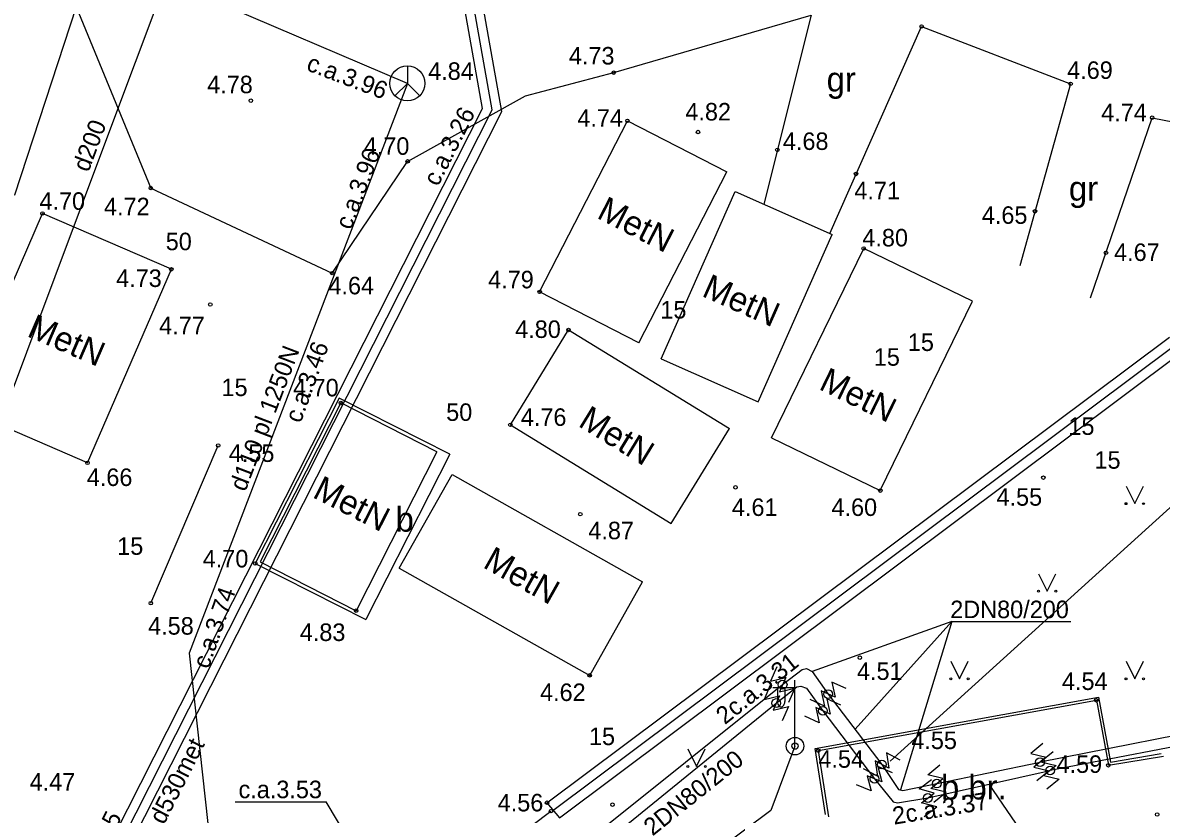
# Model space of a CAD drawing. Extents: x 484635 to 484808, y 278866 to 278977.
# Drawn here: x 484755.78 to 484788.25, y 278898.63 to 278921.23 of the extents above; entities that cross this region are included whole.
import ezdxf

# ---------------------------------------------------------------- set-up
doc = ezdxf.new("R2010")
doc.units = 0
for name, color, linetype in [('APGS_ACRL_####_####_#', 7, 'Continuous'), ('APGS_ELEM_####_####_#', 7, 'Continuous'), ('APGS_VADP_ZSPR_####_I', 7, 'Continuous'), ('BUVE_EKAS_BPAL_####_#', 7, 'Continuous'), ('BUVE_EKAS_RAKS_TKST_#', 7, 'Continuous'), ('CELI_CAPM_####_####_#', 7, 'Continuous'), ('CELI_CMAL_####_####_#', 7, 'Continuous'), ('CELI_CSEG_####_TKST_#', 7, 'Continuous'), ('CKOM_ELEM_####_####_#', 7, 'Continuous'), ('ELEK_VADP_NEDR_####_#', 7, 'Continuous'), ('GAZE_VADP_KONT_####_#', 7, 'Continuous'), ('GAZE_VADP_VSP2_####_#', 7, 'Continuous'), ('GAZE_VADP_VSP2_TKST_#', 7, 'Continuous'), ('NORB_ZOGS_KONT_####_#', 7, 'Continuous'), ('NORB_ZOGS_ZSTP_####_#', 7, 'Continuous'), ('RELJ_AATZ_####_TKST_#', 7, 'Continuous'), ('RELJ_ELEM_####_####_#', 7, 'Continuous'), ('SAKK_ELEM_####_####_#', 7, 'Continuous'), ('SAKK_ELEM_####_TKST_#', 7, 'Continuous'), ('SAKK_KKAN_####_####_I', 7, 'Continuous'), ('SAKK_KKAN_####_TKST_I', 7, 'Continuous'), ('SILT_VADP_UDEN_####_I', 7, 'Continuous'), ('SILT_VADP_UDEN_TKST_I', 7, 'Continuous'), ('SKAN_VADP_NEDR_####_#', 7, 'Continuous'), ('SKAN_VADP_NEDR_TKST_#', 7, 'Continuous'), ('TERT_DIAM_####_TKST_#', 7, 'Continuous'), ('TERT_ELEM_####_####_#', 7, 'Continuous'), ('TERT_KOKR_####_####_#', 7, 'Continuous')]:
    doc.layers.add(name, color=color, linetype=linetype)

msp = doc.modelspace()

# ---------------------------------------------------------------- linework, layer by layer
at = {"layer": 'APGS_ACRL_####_####_#'}
msp.add_lwpolyline([(484777.807, 278900.58), (484777.114, 278898.745), (484769.642, 278893.153), (484768.844, 278885.007), (484767.749, 278872.905), (484767.227, 278866.043)], dxfattribs=at)
at = {"layer": 'APGS_ELEM_####_####_#'}
for p, q in [((484777.807, 278902.247), (484777.172, 278902.242)), ((484777.307, 278902.243), (484777.307, 278901.851)), ((484777.517, 278902.245), (484777.517, 278901.851)), ((484777.807, 278900.58), (484777.807, 278902.463))]:
    msp.add_line(p, q, dxfattribs=at)
for radius in [0.25, 0.09]:
    msp.add_circle((484777.807, 278900.58), radius, dxfattribs=at)
msp.add_ellipse((484777.412, 278901.851), major_axis=(0, 0.151), ratio=0.695971, start_param=1.570796, end_param=4.712389, dxfattribs=at)
at = {"layer": 'APGS_VADP_ZSPR_####_I'}
msp.add_lwpolyline([(484777.807, 278900.58), (484777.114, 278898.745), (484769.642, 278893.153), (484768.844, 278885.007), (484767.749, 278872.905), (484767.227, 278866.043)], dxfattribs=at)
at = {"layer": 'BUVE_EKAS_BPAL_####_#'}
for p, q in [((484770.523, 278913.544), (484773.028, 278918.428)), ((484773.028, 278918.428), (484775.862, 278916.974)), ((484773.356, 278912.09), (484775.862, 278916.974)), ((484773.993, 278911.633), (484776.103, 278916.406)), ((484776.103, 278916.406), (484778.869, 278915.184)), ((484753.95, 278910.258), (484756.344, 278915.783)), ((484760.02, 278914.19), (484756.344, 278915.783)), ((484776.758, 278910.41), (484778.869, 278915.184)), ((484777.139, 278909.381), (484779.767, 278914.783)), ((484782.868, 278913.275), (484779.767, 278914.783)), ((484757.626, 278908.665), (484760.02, 278914.19)), ((484773.356, 278912.09), (484770.523, 278913.544)), ((484780.241, 278907.873), (484782.868, 278913.275)), ((484769.688, 278909.75), (484771.348, 278912.459)), ((484771.348, 278912.459), (484775.94, 278909.646)), ((484773.993, 278911.633), (484776.758, 278910.41)), ((484767.594, 278908.983), (484764.851, 278910.375)), ((484757.626, 278908.665), (484753.95, 278910.258)), ((484769.688, 278909.75), (484774.28, 278906.937)), ((484774.28, 278906.937), (484775.94, 278909.646)), ((484777.139, 278909.381), (484780.241, 278907.873)), ((484767.594, 278908.983), (484765.291, 278904.445)), ((484766.52, 278905.658), (484768.024, 278908.328)), ((484768.024, 278908.328), (484773.455, 278905.269)), ((484762.548, 278905.837), (484765.291, 278904.445)), ((484766.52, 278905.658), (484771.951, 278902.599)), ((484771.951, 278902.599), (484773.455, 278905.269))]:
    msp.add_line(p, q, dxfattribs=at)
msp.add_lwpolyline([(484764.851, 278910.375), (484762.548, 278905.837)], dxfattribs=at)
at = {"layer": 'CELI_CAPM_####_####_#'}
for p, q in [((484778.384, 278900.515), (484786.469, 278901.98)), ((484778.475, 278900.45), (484786.405, 278901.887)), ((484786.405, 278901.887), (484786.747, 278900.033)), ((484786.469, 278901.98), (484786.811, 278900.125)), ((484778.68, 278898.628), (484778.384, 278900.515)), ((484778.771, 278898.563), (484778.475, 278900.45)), ((484786.747, 278900.033), (484788.317, 278900.296)), ((484786.811, 278900.125), (484788.255, 278900.367))]:
    msp.add_line(p, q, dxfattribs=at)
at = {"layer": 'CELI_CMAL_####_####_#'}
for p, q in [((484764.807, 278910.509), (484762.414, 278905.793)), ((484767.959, 278908.91), (484764.807, 278910.509)), ((484767.959, 278908.91), (484765.565, 278904.194)), ((484762.414, 278905.793), (484765.565, 278904.194))]:
    msp.add_line(p, q, dxfattribs=at)
for points in [[(484757.301, 278921.684), (484755.548, 278916.308), (484754.577, 278916.086)], [(484757.301, 278921.684), (484759.431, 278916.509), (484764.605, 278914.081)], [(484764.605, 278914.081), (484766.759, 278917.269), (484770.124, 278919.136), (484772.638, 278919.804), (484778.27, 278921.442), (484776.916, 278916.047)], [(484778.797, 278915.215), (484781.421, 278921.121), (484785.669, 278919.483)], [(484785.669, 278919.483), (484784.22, 278914.284)], [(484786.236, 278913.375), (484787.997, 278918.515), (484788.633, 278918.391)]]:
    msp.add_lwpolyline(points, dxfattribs=at)
at = {"layer": 'CKOM_ELEM_####_####_#'}
for points in [[(484777.29, 278902.847), (484777.109, 278902.438), (484777.545, 278902.539), (484777.365, 278902.129), (484777.8, 278902.231), (484777.62, 278901.821)], [(484777.104, 278902.32), (484776.928, 278901.909), (484777.362, 278902.015), (484777.186, 278901.604), (484777.62, 278901.709), (484777.444, 278901.298)], [(484779.268, 278902.223), (484778.861, 278902.409), (484778.956, 278901.972), (484778.55, 278902.158), (484778.645, 278901.721), (484778.238, 278901.907)], [(484779.12, 278901.744), (484778.714, 278901.932), (484778.808, 278901.494), (484778.402, 278901.682), (484778.496, 278901.244), (484778.09, 278901.432)], [(484784.882, 278900.653), (484784.536, 278900.371), (484784.97, 278900.263), (484784.623, 278899.98), (484785.057, 278899.873), (484784.711, 278899.59)], [(484780.812, 278900.176), (484780.419, 278900.389), (484780.485, 278899.947), (484780.091, 278900.159), (484780.157, 278899.717), (484779.764, 278899.93)], [(484785.173, 278900.416), (484784.825, 278900.135), (484785.258, 278900.025), (484784.91, 278899.744), (484785.344, 278899.634), (484784.996, 278899.353)], [(484780.587, 278899.821), (484780.175, 278899.995), (484780.283, 278899.561), (484779.871, 278899.735), (484779.979, 278899.301), (484779.567, 278899.475)], [(484781.772, 278898.978), (484782.117, 278899.262), (484781.682, 278899.368), (484782.028, 278899.652), (484781.593, 278899.758), (484781.938, 278900.042)], [(484781.496, 278898.57), (484781.852, 278898.842), (484781.421, 278898.963), (484781.777, 278899.235), (484781.346, 278899.356), (484781.702, 278899.628)]]:
    msp.add_lwpolyline(points, dxfattribs=at)
for centre in [(484777.455, 278902.334), (484778.753, 278902.065), (484777.274, 278901.809), (484778.605, 278901.588), (484784.797, 278900.122), (484780.288, 278900.053), (484785.084, 278899.884), (484780.077, 278899.648), (484781.855, 278899.51), (484781.599, 278899.099)]:
    msp.add_circle(centre, 0.125, dxfattribs=at)
at = {"layer": 'ELEK_VADP_NEDR_####_#'}
msp.add_lwpolyline([(484780.522, 278900.153), (484790.322, 278909.033)], dxfattribs=at)
at = {"layer": 'GAZE_VADP_KONT_####_#'}
for points in [[(484750.477, 278882.479), (484757.277, 278895.824), (484768.894, 278918.779), (484766.279, 278933.523), (484765.094, 278950.654), (484769.76, 278961.533)], [(484751.36, 278883.044), (484757.749, 278895.584), (484769.446, 278918.697), (484766.805, 278933.587), (484765.632, 278950.562), (484770.25, 278961.331)]]:
    msp.add_lwpolyline(points, dxfattribs=at)
at = {"layer": 'GAZE_VADP_VSP2_####_#'}
msp.add_lwpolyline([(484750.918, 278882.762), (484757.513, 278895.704), (484769.17, 278918.738), (484766.542, 278933.555), (484765.363, 278950.608), (484770.005, 278961.432)], dxfattribs=at)
at = {"layer": 'NORB_ZOGS_KONT_####_#'}
for p, q in [((484770.732, 278898.963), (484788.487, 278912.252)), ((484771.089, 278898.537), (484788.785, 278911.787)), ((484770.732, 278898.963), (484771.089, 278898.537))]:
    msp.add_line(p, q, dxfattribs=at)
at = {"layer": 'NORB_ZOGS_ZSTP_####_#'}
msp.add_line((484770.897, 278898.742), (484788.636, 278912.019), dxfattribs=at)
msp.add_lwpolyline([(484754.908, 278886.695), (484770.847, 278898.725)], dxfattribs=at)
at = {"layer": 'RELJ_ELEM_####_####_#'}
for centre in [(484781.421, 278921.121), (484772.638, 278919.804), (484785.669, 278919.483), (484762.287, 278919.003), (484773.028, 278918.428), (484787.997, 278918.515), (484775.039, 278918.107), (484777.306, 278917.598), (484766.759, 278917.269), (484779.55, 278916.91), (484759.431, 278916.509), (484756.344, 278915.783), (484784.655, 278915.845), (484779.767, 278914.783), (484786.677, 278914.66), (484760.02, 278914.19), (484764.605, 278914.081), (484770.523, 278913.544), (484761.128, 278913.183), (484771.348, 278912.459), (484764.851, 278910.375), (484769.688, 278909.75), (484761.352, 278909.162), (484757.626, 278908.665), (484776.109, 278907.965), (484784.892, 278908.244), (484780.241, 278907.873), (484771.683, 278907.201), (484762.414, 278905.793), (484759.435, 278904.659), (484765.291, 278904.445), (484779.656, 278903.104), (484771.951, 278902.599), (484786.405, 278901.887), (484778.475, 278900.45), (484786.747, 278900.033), (484770.732, 278898.963), (484772.602, 278898.907), (484770.847, 278898.725), (484788.14, 278898.629)]:
    msp.add_circle(centre, 0.05, dxfattribs=at)
at = {"layer": 'SAKK_ELEM_####_####_#'}
msp.add_line((484766.75, 278919.495), (484767.104, 278919.141), dxfattribs=at)
msp.add_lwpolyline([(484766.75, 278919.995), (484766.75, 278919.495), (484766.396, 278919.141)], dxfattribs=at)
msp.add_circle((484766.75, 278919.495), 0.5, dxfattribs=at)
at = {"layer": 'SAKK_KKAN_####_####_I'}
msp.add_line((484766.75, 278919.495), (484754.941, 278924.541), dxfattribs=at)
for points in [[(484766.75, 278919.495), (484760.526, 278903.237)], [(484760.526, 278903.237), (484761.675, 278892.732), (484761.895, 278888.193)]]:
    msp.add_lwpolyline(points, dxfattribs=at)
at = {"layer": 'SILT_VADP_UDEN_####_I'}
for p, q in [((484768.082, 278894.84), (484777.455, 278902.334)), ((484767.961, 278894.241), (484777.274, 278901.809))]:
    msp.add_line(p, q, dxfattribs=at)
for points in [[(484777.455, 278902.334), (484778.009, 278902.769), (484778.133, 278902.792), (484778.293, 278902.707), (484778.753, 278902.065)], [(484777.274, 278901.809), (484777.856, 278902.276), (484777.975, 278902.291), (484778.134, 278902.229), (484778.605, 278901.588)], [(484796.569, 278902.446), (484784.797, 278900.122)], [(484796.869, 278902.149), (484785.084, 278899.884)], [(484778.753, 278902.065), (484780.288, 278900.053)], [(484778.605, 278901.588), (484780.077, 278899.648)], [(484780.288, 278900.053), (484780.76, 278899.342), (484780.884, 278899.313), (484781.855, 278899.51)], [(484781.599, 278899.099), (484785.084, 278899.884)], [(484781.855, 278899.51), (484784.797, 278900.122)], [(484780.077, 278899.648), (484780.611, 278898.991), (484780.736, 278898.957), (484781.599, 278899.099)]]:
    msp.add_lwpolyline(points, dxfattribs=at)
at = {"layer": 'SILT_VADP_UDEN_TKST_I'}
for p, q in [((484782.278, 278904.139), (484778.293, 278902.707)), ((484782.278, 278904.139), (484779.521, 278901.059)), ((484782.278, 278904.139), (484780.822, 278899.328)), ((484782.278, 278904.139), (484785.674, 278904.139)), ((484761.842, 278898.988), (484764.438, 278898.988)), ((484767.585, 278893.684), (484764.438, 278898.988))]:
    msp.add_line(p, q, dxfattribs=at)
msp.add_lwpolyline([(484784.493, 278897.806), (484783.342, 278899.492)], dxfattribs=at)
at = {"layer": 'SKAN_VADP_NEDR_####_#'}
msp.add_lwpolyline([(484751.85, 278901.026), (484758.323, 278918.301), (484762.372, 278929.106)], dxfattribs=at)
at = {"layer": 'TERT_ELEM_####_####_#'}
for p, q in [((484787.25, 278908), (484787.5, 278907.5)), ((484787.5, 278907.5), (484787.75, 278908)), ((484784.75, 278905.5), (484785, 278905)), ((484785, 278905), (484785.25, 278905.5)), ((484782.25, 278903), (484782.5, 278902.5)), ((484782.5, 278902.5), (484782.75, 278903)), ((484787.25, 278903), (484787.5, 278902.5)), ((484787.5, 278902.5), (484787.75, 278903)), ((484774.75, 278900.5), (484775, 278900)), ((484775, 278900), (484775.25, 278900.5))]:
    msp.add_line(p, q, dxfattribs=at)
for centre, radius in [((484787.25, 278907.5), 0.028), ((484787.75, 278907.5), 0.0263), ((484784.75, 278905), 0.028), ((484785.25, 278905), 0.0263), ((484782.25, 278902.5), 0.028), ((484782.75, 278902.5), 0.0263), ((484787.25, 278902.5), 0.028), ((484787.75, 278902.5), 0.0263), ((484774.75, 278900), 0.028), ((484775.25, 278900), 0.0263)]:
    msp.add_circle(centre, radius, dxfattribs=at)
at = {"layer": 'TERT_KOKR_####_####_#'}
msp.add_lwpolyline([(484759.435, 278904.659), (484761.352, 278909.162)], dxfattribs=at)

# ---------------------------------------------------------------- texts
at = {"layer": 'BUVE_EKAS_RAKS_TKST_#'}
for rotation, p in [(332.8417, (484772.123, 278915.669)), (336.1501, (484775.119, 278913.433)), (336.5704, (484755.871, 278912.289)), (334.0635, (484778.457, 278910.779)), (328.5089, (484771.594, 278909.73)), (333.0941, (484764.015, 278907.694)), (330.6113, (484768.875, 278905.695))]:
    msp.add_text('MetN', height=0.7, rotation=rotation, dxfattribs=at).set_placement(p)
at = {"layer": 'CELI_CSEG_####_TKST_#'}
for s, p in [('gr', (484778.711, 278919.262)), ('gr', (484785.621, 278916.146)), ('b', (484766.415, 278906.701)), ('b.br.', (484781.973, 278899.056))]:
    msp.add_text(s, height=0.7, dxfattribs=at).set_placement(p)
at = {"layer": 'GAZE_VADP_VSP2_TKST_#'}
for s, p in [('c.a.3.26', (484767.624, 278916.531)), ('d530met', (484759.808, 278898.316)), ('c.a.3.05', (484757.544, 278896.432))]:
    msp.add_text(s, height=0.5, rotation=63.157, dxfattribs=at).set_placement(p)
at = {"layer": 'RELJ_AATZ_####_TKST_#'}
for s, p in [('4.73', (484771.358, 278920.035)), ('4.69', (484785.571, 278919.624)), ('4.78', (484761.04, 278919.215)), ('4.74', (484771.599, 278918.258)), ('4.82', (484774.681, 278918.437)), ('4.74', (484786.542, 278918.414)), ('4.68', (484777.462, 278917.596)), ('4.70', (484765.507, 278917.457)), ('4.71', (484779.502, 278916.187)), ('4.70', (484756.256, 278915.887)), ('4.72', (484758.098, 278915.732)), ('4.65', (484783.137, 278915.487)), ('4.80', (484779.729, 278914.842)), ('4.67', (484786.909, 278914.427)), ('4.73', (484758.443, 278913.685)), ('4.64', (484764.499, 278913.475)), ('4.79', (484769.055, 278913.646)), ('4.77', (484759.67, 278912.335)), ('4.80', (484769.826, 278912.23)), ('4.70', (484763.491, 278910.562)), ('4.76', (484769.987, 278909.72)), ('4.55', (484761.657, 278908.691)), ('4.66', (484757.606, 278908.004)), ('4.55', (484783.556, 278907.442)), ('4.61', (484776.008, 278907.149)), ('4.60', (484778.849, 278907.149)), ('4.87', (484771.913, 278906.484)), ('4.70', (484760.914, 278905.68)), ('4.58', (484759.356, 278903.761)), ('4.83', (484763.682, 278903.58)), ('4.51', (484779.576, 278902.469)), ('4.54', (484785.423, 278902.182)), ('4.62', (484770.535, 278901.867)), (' 4.55', (484780.94, 278900.496)), ('4.54', (484778.475, 278899.962)), ('4.59', (484785.268, 278899.816)), ('4.47', (484755.976, 278899.311)), ('4.56', (484769.327, 278898.716))]:
    msp.add_text(s, height=0.5, dxfattribs=at).set_placement(p)
at = {"layer": 'SAKK_ELEM_####_TKST_#'}
msp.add_text('4.84', height=0.5, dxfattribs=at).set_placement((484767.344, 278919.596))
at = {"layer": 'SAKK_KKAN_####_TKST_I'}
for s, rotation, p in [('c.a.3.96', 339.0518, (484763.84, 278919.882)), ('c.a.3.96', 69.0518, (484765.14, 278915.291)), ('d110 pl 1250N', 69.0518, (484762.129, 278907.822)), ('c.a.3.46', 70.0188, (484763.705, 278909.775)), ('c.a.3.74', 70.7279, (484761.077, 278902.759))]:
    msp.add_text(s, height=0.5, rotation=rotation, dxfattribs=at).set_placement(p)
at = {"layer": 'SILT_VADP_UDEN_TKST_I'}
for s, p in [('2DN80/200', (484782.236, 278904.232)), ('c.a.3.53', (484761.935, 278899.093))]:
    msp.add_text(s, height=0.5, dxfattribs=at).set_placement(p)
for s, rotation, p in [('2c.a.3.31', 38.6435, (484775.808, 278901.175)), ('2DN80/200', 38.6435, (484773.745, 278897.999)), ('2c.a.3.37', 9.3439, (484780.632, 278898.336))]:
    msp.add_text(s, height=0.5, rotation=rotation, dxfattribs=at).set_placement(p)
at = {"layer": 'SKAN_VADP_NEDR_TKST_#'}
msp.add_text('d200', height=0.5, rotation=69.4583, dxfattribs=at).set_placement((484757.654, 278916.941))
at = {"layer": 'TERT_DIAM_####_TKST_#'}
for s, p in [('50', (484759.858, 278914.734)), ('15', (484773.967, 278912.784)), ('15', (484781.027, 278911.858)), ('15', (484780.056, 278911.436)), ('15', (484761.449, 278910.57)), ('50', (484767.858, 278909.862)), ('15', (484785.606, 278909.462)), ('15', (484786.351, 278908.497)), ('15', (484758.474, 278906.039)), ('15', (484771.931, 278900.608))]:
    msp.add_text(s, height=0.5, dxfattribs=at).set_placement(p)

doc.saveas('drawing.dxf')
